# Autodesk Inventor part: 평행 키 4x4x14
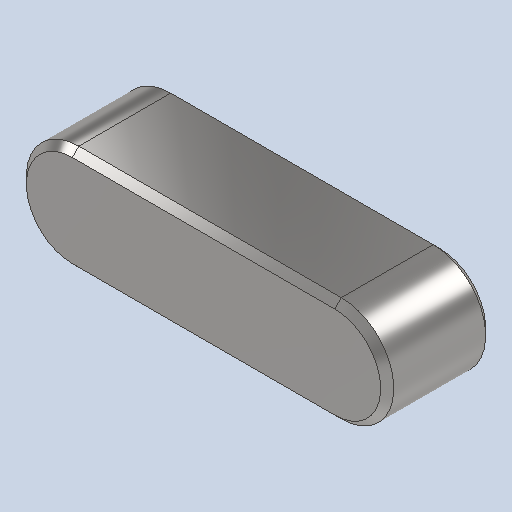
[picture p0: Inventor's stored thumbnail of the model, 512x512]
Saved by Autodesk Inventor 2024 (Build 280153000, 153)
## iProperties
Created: 2024-12
Part Number: 평행 키 4x4x14
Material: 강철, 연강
Description: 키 및 해당 키홈
Document SubType Name: Modeling
Designer: user
Density: 7.85 g/cm^3
Appearance: 기본값
Author: jhkim
Sending System: Autodesk Inventor 2025
Preprocessor: ST-DEVELOPER v20
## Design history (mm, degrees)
node "평행 키 4x4x141"
node "솔리드1"
body "Solid1"
